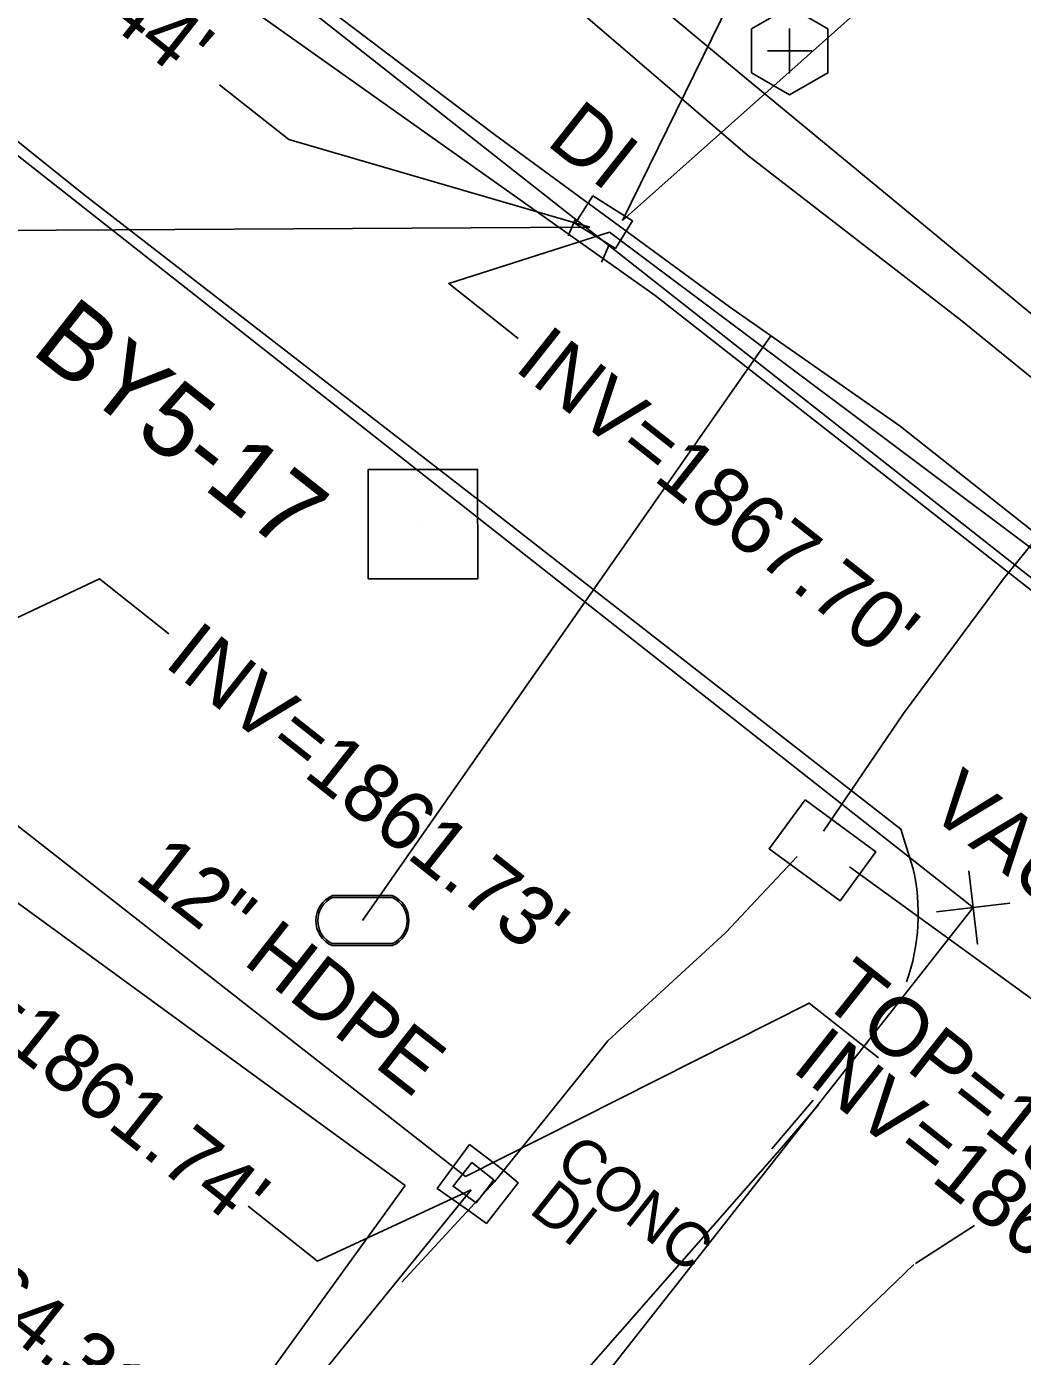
# Model space of a CAD drawing. Extents: x 553786 to 558838, y 502329 to 507342.
# Drawn here: x 557854.1 to 557921.7, y 506619.3 to 506709.4 of the extents above; entities that cross this region are included whole.
import ezdxf

# ---------------------------------------------------------------- set-up
doc = ezdxf.new("R2010")
doc.units = 0
for name, color, linetype in [('CTL Secondary Horizontal and Vertical Text', 7, 'Continuous'), ('Exist Hydrographic Top of Bank', 7, 'Continuous'), ('Exist Structure Minor Drop Inlet', 7, 'Continuous'), ('Exist Structure Minor Drop Inlet Text', 7, 'Continuous'), ('Exist Structure Minor Drop Inlet Top Elevation', 7, 'Continuous'), ('Exist Structure Minor Paved Ditch or Gutter Text', 7, 'Continuous'), ('Exist Structure Minor Pipes CMP 15 Inch', 7, 'Continuous'), ('Exist Structure Minor Pipes CMP 15 Inch Invert', 7, 'Continuous'), ('Exist Structure Minor Pipes CMP 15 Inch Leader', 7, 'Continuous'), ('Exist Structure Minor Pipes HDPE 12 Inch', 7, 'Continuous'), ('Exist Structure Minor Pipes HDPE 12 Inch Invert', 7, 'Continuous'), ('Exist Structure Minor Pipes HDPE 12 Inch Leader', 7, 'Continuous'), ('Exist Structure Minor Pipes HDPE 12 Inch Text', 7, 'Continuous'), ('Exist Utilities Telephone Pedestal Text', 7, 'Continuous'), ('Exist Vertical Profile Ground Line', 7, 'Continuous'), ('Prop CMT DNC', 7, 'Continuous'), ('Prop CMT Slope Grass', 7, 'Continuous'), ('Prop Drainage Structure Drop Inlet Grate 840 16 Label', 7, 'Continuous'), ('Prop Drainage Structure Pipe Alternate 18in', 7, 'Continuous'), ('Prop Drainage Structure Pipe Alternate 24in', 7, 'Continuous'), ('Prop Drainage Structure Pipe Alternate 36in', 7, 'Continuous'), ('Prop Drainage Structure Pipe RCP 15in Class III Label', 7, 'Continuous'), ('Prop Drainage Structure Pipe RCP 30in Class III Label', 7, 'Continuous'), ('Prop Drainage Structure Pipe Removal', 7, 'Continuous'), ('Prop Drainage Structure Plot Symbol 50 Scale', 7, 'Continuous'), ('Prop Drainage Structure Tops and Inverts LABEL', 7, 'Continuous'), ('Prop Erosion Rip Rap Pad Outlet for Jurisdictional Stream CELL', 7, 'Continuous'), ('Prop Erosion Rip Rap Single Stone CELL', 7, 'Continuous'), ('Prop XS SE Text', 7, 'Continuous')]:
    doc.layers.add(name, color=color, linetype=linetype)

# ---------------------------------------------------------------- blocks, each defined once
blk = doc.blocks.new('CTL SECONDARY HORIZONTAL AND VERTICAL')
at = {"layer": 'Prop Drainage Structure Pipe Alternate 18in'}
blk.add_line((0, 0), (0, 0), dxfattribs=at)
blk.add_lwpolyline([(-0.1043, 0.0004), (0.0005, 0.1052), (0.1055, 0.0002), (0.0007, -0.1047)], close=True, dxfattribs=at)
blk = doc.blocks.new('EXIST UTILITIES WATER METER')
at = {"layer": 'Prop Drainage Structure Drop Inlet Grate 840 16 Label'}
blk.add_line((0, 0), (0, 0), dxfattribs=at)
for points in [[(-0.0408, 0.034), (0.0408, 0.034)], [(-0.0408, 0.0312), (0.0408, 0.0312)], [(0.0408, -0.0312), (-0.0413, -0.0312)], [(0.0408, -0.034), (-0.0413, -0.034)]]:
    blk.add_lwpolyline(points, dxfattribs=at)
for centre, radius, start, end in [((-0.0261, -0.0001), 0.0371, 113.178, 245.9794), ((-0.0259, -0.0001), 0.0347, 115.3009, 243.7824), ((0.0259, 0), 0.0371, 293.6483, 66.3084), ((0.0261, 0), 0.0345, 295.1272, 64.8728)]:
    blk.add_arc(centre, radius, start, end, dxfattribs=at)

msp = doc.modelspace()

# ---------------------------------------------------------------- linework, layer by layer
at = {"layer": 'Exist Hydrographic Top of Bank'}
for points in [[(557951.524, 506705.993), (557944.731, 506698.946), (557932.414, 506685.267), (557926.501, 506679.549), (557920.382, 506672.004), (557913.586, 506662.859), (557908.169, 506654.896)], [(557906.391, 506653.179), (557901.554, 506648.025), (557893.533, 506640.669), (557885.865, 506631.101), (557879.577, 506624.312)], [(557909.941, 506652.467), (557928.59, 506638.958), (557968.674, 506612.217), (558004.693, 506586.702), (558028.818, 506567.265), (558064.953, 506539.377), (558090.153, 506521.485), (558129.491, 506492.79), (558158.115, 506470.169), (558184.374, 506448.454), (558219.377, 506421.65), (558231.508, 506411.308), (558244.363, 506401.586), (558255.043, 506392.873), (558256.824, 506385.422)]]:
    msp.add_lwpolyline(points, dxfattribs=at)
at = {"layer": 'Exist Structure Minor Drop Inlet'}
for points in [[(557894.059, 506694.388), (557891.325, 506696.081), (557892.53, 506697.955), (557895.219, 506696.259), (557894.059, 506694.388)], [(557885.822, 506631.253), (557884.323, 506632.429), (557883.051, 506630.816), (557884.616, 506629.694), (557885.822, 506631.253)]]:
    msp.add_lwpolyline(points, dxfattribs=at)
at = {"layer": 'Exist Structure Minor Pipes CMP 15 Inch'}
for p, q in [((557892.315, 506695.849), (557773.483, 506695.176)), ((558034.334, 506590.114), (557893.663, 506695.491))]:
    msp.add_line(p, q, dxfattribs=at)
at = {"layer": 'Exist Structure Minor Pipes CMP 15 Inch Leader'}
for points in [[(557894.538, 506696.28), (557905.461, 506718.555), (557900.755, 506722.276)], [(557892.315, 506695.849), (557871.912, 506701.775), (557867.206, 506705.497)]]:
    msp.add_lwpolyline(points, dxfattribs=at)
at = {"layer": 'Exist Structure Minor Pipes HDPE 12 Inch'}
for p, q in [((557894.538, 506696.28), (557950.799, 506746.431)), ((557883.881, 506631.464), (557842.252, 506664.054)), ((557884.276, 506630.561), (557854.402, 506593.844))]:
    msp.add_line(p, q, dxfattribs=at)
at = {"layer": 'Exist Structure Minor Pipes HDPE 12 Inch Leader'}
for points in [[(557893.663, 506695.491), (557882.756, 506692.016), (557887.462, 506688.295)], [(557842.252, 506664.054), (557859.058, 506671.99), (557863.764, 506668.268)], [(557883.881, 506631.464), (557907.194, 506643.234), (557911.9, 506639.512)], [(557884.276, 506630.561), (557873.861, 506625.738), (557869.155, 506629.459)]]:
    msp.add_lwpolyline(points, dxfattribs=at)
at = {"layer": 'Exist Vertical Profile Ground Line'}
msp.add_lwpolyline([(557913.084, 506813.342), (557906.869, 506807.424), (557903.763, 506805.425), (557899.227, 506803.082), (557894.138, 506802.119), (557888.573, 506799.224), (557879.133, 506789.507), (557871.119, 506778.794), (557854.777, 506758.764), (557850.029, 506750.87), (557849.869, 506748.384), (557850.854, 506745.691), (557856.304, 506740.46), (557866.069, 506732.886), (557880.785, 506720.639), (557892.018, 506710.139), (557903.012, 506700.727), (557917.463, 506689.549), (557930.53, 506678.943), (557935.077, 506674.753), (557956.227, 506656.911), (557979.423, 506638.698), (557993.477, 506630.447), (557997.106, 506628.628)], dxfattribs=at)
at = {"layer": 'Prop CMT DNC'}
msp.add_line((557918.314, 506649.716), (557918.314, 506649.716), dxfattribs=at)
msp.add_lwpolyline([(557918.017, 506652.198), (557918.61, 506647.233), (557918.314, 506649.716), (557920.796, 506650.012), (557915.831, 506649.419)], dxfattribs=at)
at = {"layer": 'Prop CMT Slope Grass'}
msp.add_lwpolyline([(557856.858, 506744.225), (557902.929, 506705.915), (557929.575, 506683.918)], dxfattribs=at)
at = {"layer": 'Prop Drainage Structure Pipe Alternate 24in'}
msp.add_line((557904.603, 506688.469), (557876.902, 506648.824), dxfattribs=at)
msp.add_lwpolyline([(557781.488, 506782.055), (557812.493, 506757.286), (557852.111, 506727.606), (557885.847, 506702.112), (557901.783, 506690.439), (557913.357, 506682.352), (557957.702, 506647.239), (557985.503, 506624.804), (558024.874, 506594.383), (558058.457, 506565.348), (558080.435, 506547.162), (558106.812, 506525.595), (558129.018, 506509.215), (558127.193, 506506.921), (558119.501, 506495.814), (558106.122, 506476.086), (558102.443, 506470.499), (558089.843, 506453.112)], dxfattribs=at)
at = {"layer": 'Prop Drainage Structure Pipe Alternate 36in'}
for p, q in [((557905.019, 506633.084), (557907.837, 506636.342)), ((557918.404, 506628.15), (557914.401, 506625.576))]:
    msp.add_line(p, q, dxfattribs=at)
for points in [[(557942.771, 506661.496), (557928.532, 506667.97), (557926.466, 506667.938), (557896.746, 506691.215), (557868.366, 506711.353), (557841.406, 506733.223), (557815.868, 506752.942), (557815.175, 506755.367), (557818.066, 506757.602), (557816.114, 506763.023), (557814.286, 506766.048), (557812.819, 506765.301), (557812.809, 506762.917), (557811.454, 506760.704), (557808.055, 506759.419), (557782.636, 506780.329), (557758.662, 506799.481), (557745.755, 506809.907)], [(557914.234, 506652.406), (557913.419, 506655.027), (557884.822, 506677.31), (557858, 506698.043), (557846.54, 506707.229)]]:
    msp.add_lwpolyline(points, dxfattribs=at)
msp.add_ellipse((557900.837, 506649.31), major_axis=(2.728, -13.552), ratio=0.994668, start_param=1.030621, end_param=1.599093, dxfattribs=at)
at = {"layer": 'Prop Drainage Structure Pipe RCP 15in Class III Label'}
for p, q in [((557828.715, 506745.656), (557972.77, 506632.319)), ((557806.702, 506737.527), (557918.314, 506649.716))]:
    msp.add_line(p, q, dxfattribs=at)
at = {"layer": 'Prop Drainage Structure Pipe RCP 30in Class III Label'}
msp.add_line((557905.874, 506707.793), (557905.874, 506707.793), dxfattribs=at)
msp.add_lwpolyline([(557903.296, 506709.288), (557903.29, 506706.308), (557905.869, 506704.813), (557908.452, 506706.299), (557908.457, 506709.279), (557905.879, 506710.773)], close=True, dxfattribs=at)
msp.add_lwpolyline([(557905.874, 506709.306), (557905.874, 506706.281), (557905.874, 506707.793), (557907.386, 506707.793), (557904.361, 506707.793)], dxfattribs=at)
at = {"layer": 'Prop Drainage Structure Pipe Removal'}
msp.add_lwpolyline([(557906.921, 506657.016), (557911.728, 506653.482), (557909.289, 506650.165), (557904.482, 506653.699)], close=True, dxfattribs=at)
at = {"layer": 'Prop Drainage Structure Plot Symbol 50 Scale'}
for points in [[(557905.019, 506633.084), (557889.994, 506615.952), (557877.358, 506603.776), (557869.534, 506596.09), (557859.905, 506586.296), (557856.124, 506582.195)], [(557914.288, 506625.504), (557902.934, 506614.559), (557891.962, 506602.325), (557886.689, 506595.808), (557878.19, 506585.572), (557870.317, 506575.491), (557868.29, 506572.84)]]:
    msp.add_lwpolyline(points, dxfattribs=at)
at = {"layer": 'Prop Drainage Structure Tops and Inverts LABEL'}
msp.add_line((557904.664, 506633.349), (557907.477, 506636.648), dxfattribs=at)
at = {"layer": 'Prop Erosion Rip Rap Pad Outlet for Jurisdictional Stream CELL'}
msp.add_lwpolyline([(557879.807, 506630.873), (557852.181, 506592.697), (557846.145, 506596.898), (557800.028, 506533.439), (557763.516, 506559.979), (557816.37, 506631.885), (557823.285, 506626.255), (557845.369, 506655.959)], close=True, dxfattribs=at)
at = {"layer": 'Prop Erosion Rip Rap Single Stone CELL'}
for p, q in [((557891.321, 506696.353), (557890.845, 506695.256)), ((557893.624, 506694.639), (557893.12, 506693.461))]:
    msp.add_line(p, q, dxfattribs=at)
msp.add_lwpolyline([(557884.159, 506633.634), (557886.417, 506631.921), (557887.471, 506631.042), (557885.304, 506628.288), (557884.093, 506629.169), (557881.976, 506630.667), (557884.159, 506633.634)], dxfattribs=at)
at = {"layer": 'Prop XS SE Text'}
msp.add_line((557789.083, 506485.458), (557918.314, 506649.716), dxfattribs=at)

# ---------------------------------------------------------------- block references
at = {"layer": 'Prop Drainage Structure Drop Inlet Grate 840 16 Label', "xscale": 50, "yscale": 50}
msp.add_blockref('EXIST UTILITIES WATER METER', (557876.902, 506648.824), dxfattribs=at)
at = {"layer": 'Prop Drainage Structure Pipe Alternate 18in', "xscale": 50, "yscale": 49.99999999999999, "rotation": 44.99999999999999}
msp.add_blockref('CTL SECONDARY HORIZONTAL AND VERTICAL', (557880.991, 506675.678), dxfattribs=at)

# ---------------------------------------------------------------- texts
at = {"layer": 'CTL Secondary Horizontal and Vertical Text'}
msp.add_text('BY5-17', height=5, rotation=321.80596, dxfattribs=at).set_placement((557854.325, 506687.373))
at = {"layer": 'Exist Structure Minor Drop Inlet Text'}
for height, p in [(4, (557889.276, 506701.493)), (3, (557888.113, 506629.073))]:
    msp.add_text('DI', height=height, rotation=321.66667, dxfattribs=at).set_placement(p)
at = {"layer": 'Exist Structure Minor Drop Inlet Top Elevation'}
for s, p in [("TOP=1864.39'", (557907.838, 506643.362)), ("TOP=1864.31'", (557834.319, 506635.357))]:
    msp.add_text(s, height=4, rotation=321.66667, dxfattribs=at).set_placement(p)
at = {"layer": 'Exist Structure Minor Paved Ditch or Gutter Text'}
msp.add_text('CONC', height=3, rotation=321.66667, dxfattribs=at).set_placement((557889.84, 506632.193))
at = {"layer": 'Exist Structure Minor Pipes CMP 15 Inch Invert'}
for s, p in [("INV=1866.44'", (557839.225, 506725.77)), ("INV=1867.70'", (557887.095, 506686.217))]:
    msp.add_text(s, height=4, rotation=321.66667, dxfattribs=at).set_placement(p)
at = {"layer": 'Exist Structure Minor Pipes HDPE 12 Inch Invert'}
for s, p in [("INV=1861.73'", (557863.354, 506666.158)), ("INV=1861.74'", (557843.037, 506647.858)), ("INV=1861.81'", (557905.916, 506638.709)), ("INV=1861.80'", (557832.328, 506630.489))]:
    msp.add_text(s, height=4, rotation=321.66667, dxfattribs=at).set_placement(p)
at = {"layer": 'Exist Structure Minor Pipes HDPE 12 Inch Text'}
msp.add_text('12" HDPE', height=4, rotation=321.94376, dxfattribs=at).set_placement((557861.357, 506651.703))
at = {"layer": 'Exist Utilities Telephone Pedestal Text'}
msp.add_text('VAULT', height=4, rotation=321.66667, dxfattribs=at).set_placement((557915.106, 506656.179))

doc.saveas('drawing.dxf')
